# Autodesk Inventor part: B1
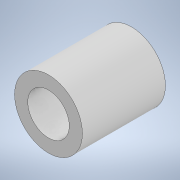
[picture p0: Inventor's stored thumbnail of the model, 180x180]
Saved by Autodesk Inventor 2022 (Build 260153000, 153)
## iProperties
Created: 2024-12
Part Number: B1
Material: 一般
Document SubType Name: Modeling
Designer: jsat7
Density: 1 g/cm^3
Appearance: 既定
Author: jsat7
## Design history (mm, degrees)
sketch "スケッチ1"
  geometry: C1 r 2.45 at (0, 0); C2 r 1.5 at (0, 0); 1 further point
  constraints: 2 centre point, 2 coincident
  dimensions: "d0" = 4.9 diameter of C1; "d1" = 3 diameter of C2
extrude "押し出し1" new body sketch "スケッチ1" distance "d2" = 6; taper "d3" = 0 deg
node "ソリッド1"
